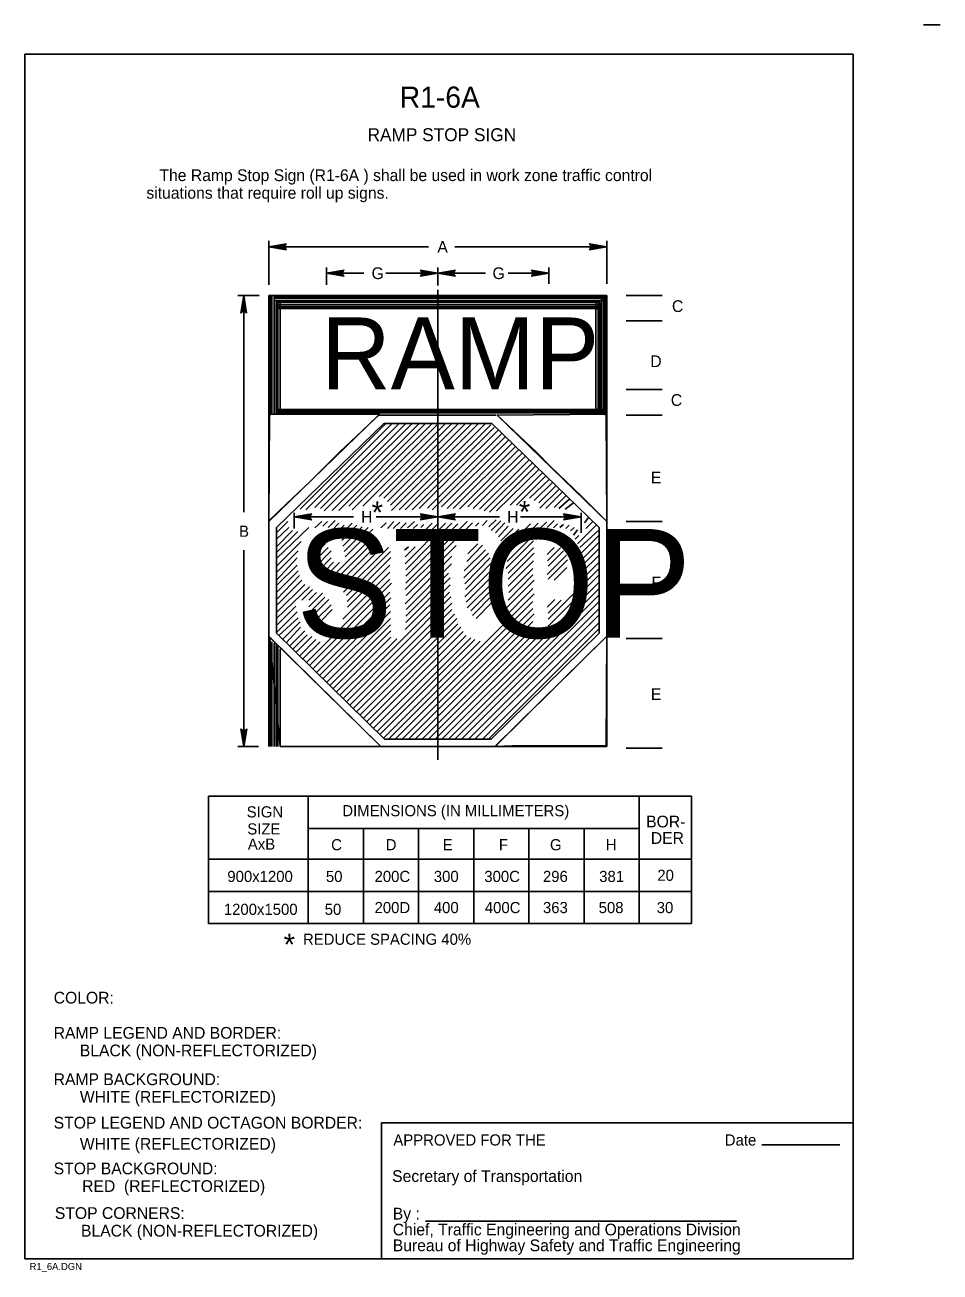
# Model space of a CAD drawing. Extents: x -0.162 to 0.195, y -0.006 to 0.263.
# Drawn here: x 0 to 0.195, y -0.0028 to 0.2627 of the extents above; entities that cross this region are included whole.
import ezdxf

# ---------------------------------------------------------------- set-up
doc = ezdxf.new("R2010")
doc.units = 0
for name, color, linetype in [('1', 7, 'Continuous'), ('2', 7, 'Continuous'), ('3', 7, 'Continuous')]:
    doc.layers.add(name, color=color, linetype=linetype)

# ---------------------------------------------------------------- blocks, each defined once
blk = doc.blocks.new('RARROW')
at = {"layer": '3'}
for p, q in [((-2.156, 0.285), (-2.2665, 0.384625)), ((-2.2665, 0.384625), (0, 0)), ((0, 0), (-2.2665, -0.379125)), ((-2.156, 0.285), (-2.075625, 0.12075)), ((0, 0), (-2.156, 0.285)), ((-2.14975, -0.2705), (0, 0)), ((-2.075625, 0.12075), (0, 0)), ((0, 0), (-2.074, -0.108)), ((-2.2665, -0.379125), (-2.14975, -0.2705)), ((-2.074, -0.108), (-2.14975, -0.2705))]:
    blk.add_line(p, q, dxfattribs=at)

msp = doc.modelspace()

# ---------------------------------------------------------------- linework, layer by layer
at = {"layer": '1'}
for p, q in [((0.195, 0.26275), (0.1915, 0.26275)), ((0.1765, 0.2565), (0, 0.2565)), ((0, 0.2565), (0, 0)), ((0.1765, 0), (0.1765, 0.2565)), ((0.088, 0.20638), (0.088, 0.10625)), ((0.05738, 0.15888), (0.05738, 0.1555)), ((0.1185, 0.15888), (0.1185, 0.15463)), ((0.076, 0.029), (0.1765, 0.029)), ((0.076, 0.029), (0.076, 0)), ((0.157, 0.02425), (0.17363, 0.02425)), ((0.08538, 0.008), (0.15163, 0.008)), ((0, 0), (0.1765, 0))]:
    msp.add_line(p, q, dxfattribs=at)
at = {"layer": '3'}
for p, q in [((0.052, 0.20738), (0.052, 0.21675)), ((0.086, 0.2155), (0.052, 0.2155)), ((0.09162, 0.2155), (0.124, 0.2155)), ((0.124, 0.20763), (0.124, 0.21675)), ((0.06425, 0.20738), (0.06425, 0.21113)), ((0.07225, 0.20988), (0.06425, 0.20988)), ((0.07687, 0.20988), (0.088, 0.20988)), ((0.088, 0.20725), (0.088, 0.21113)), ((0.09813, 0.20988), (0.088, 0.20988)), ((0.103, 0.20988), (0.11163, 0.20988)), ((0.11163, 0.20763), (0.11163, 0.21113)), ((0.04988, 0.20513), (0.04537, 0.20513)), ((0.04662, 0.159), (0.04662, 0.20513)), ((0.052, 0.20513), (0.124, 0.20513)), ((0.052, 0.20513), (0.052, 0.10912)), ((0.05225, 0.17963), (0.05225, 0.205)), ((0.05262, 0.17988), (0.05262, 0.205)), ((0.05312, 0.17975), (0.05312, 0.205)), ((0.05325, 0.20488), (0.12312, 0.20488)), ((0.05325, 0.2045), (0.12312, 0.2045)), ((0.12287, 0.17975), (0.12287, 0.205)), ((0.12325, 0.17988), (0.12325, 0.205)), ((0.12362, 0.17963), (0.12362, 0.205)), ((0.124, 0.20513), (0.124, 0.10912)), ((0.12812, 0.20513), (0.13575, 0.20513)), ((0.05325, 0.204), (0.12312, 0.204)), ((0.0535, 0.20363), (0.1225, 0.20363)), ((0.0535, 0.17975), (0.0535, 0.20363)), ((0.0535, 0.20312), (0.1225, 0.20312)), ((0.0535, 0.20275), (0.1225, 0.20275)), ((0.0535, 0.20237), (0.1225, 0.20237)), ((0.05387, 0.18088), (0.05387, 0.20363)), ((0.05437, 0.18088), (0.05437, 0.20363)), ((0.12162, 0.18088), (0.12162, 0.20363)), ((0.12212, 0.18088), (0.12212, 0.20363)), ((0.1225, 0.17975), (0.1225, 0.20363)), ((0.12812, 0.19975), (0.13575, 0.19975)), ((0.12812, 0.18513), (0.13575, 0.18513)), ((0.0535, 0.18088), (0.124, 0.18088)), ((0.07537, 0.17963), (0.052, 0.157)), ((0.0535, 0.1805), (0.124, 0.1805)), ((0.0535, 0.18013), (0.124, 0.18013)), ((0.07537, 0.17963), (0.10038, 0.17963)), ((0.10063, 0.17963), (0.124, 0.157)), ((0.12812, 0.17963), (0.13575, 0.17963)), ((0.0765, 0.17788), (0.05362, 0.15575)), ((0.05863, 0.15963), (0.07687, 0.17788)), ((0.05988, 0.1595), (0.07825, 0.17788)), ((0.06175, 0.16), (0.07975, 0.17788)), ((0.063, 0.15975), (0.08113, 0.17788)), ((0.06375, 0.15925), (0.0825, 0.17788)), ((0.0655, 0.15938), (0.084, 0.17788)), ((0.06688, 0.15938), (0.08538, 0.17788)), ((0.069, 0.16025), (0.08675, 0.17788)), ((0.06975, 0.1595), (0.08812, 0.17788)), ((0.072, 0.16025), (0.08962, 0.17788)), ((0.0755, 0.16237), (0.091, 0.17788)), ((0.0765, 0.17788), (0.0995, 0.17788)), ((0.0765, 0.162), (0.09237, 0.17788)), ((0.07725, 0.16125), (0.09388, 0.17788)), ((0.07787, 0.1605), (0.09525, 0.17788)), ((0.07812, 0.15938), (0.09663, 0.17788)), ((0.07975, 0.1595), (0.09813, 0.17788)), ((0.081, 0.1595), (0.09925, 0.17763)), ((0.0825, 0.1595), (0.1, 0.177)), ((0.084, 0.15975), (0.10088, 0.1765)), ((0.08575, 0.15988), (0.10163, 0.17575)), ((0.0995, 0.17788), (0.12237, 0.15575)), ((0.08675, 0.1595), (0.10238, 0.17513)), ((0.08875, 0.16012), (0.10313, 0.17438)), ((0.09, 0.15975), (0.10388, 0.17375)), ((0.09125, 0.15975), (0.1045, 0.173)), ((0.09262, 0.15963), (0.10525, 0.17238)), ((0.09438, 0.16012), (0.106, 0.17162)), ((0.0955, 0.15975), (0.10662, 0.17087)), ((0.09688, 0.15963), (0.1075, 0.17025)), ((0.09788, 0.15925), (0.10812, 0.1695)), ((0.099, 0.159), (0.10887, 0.16887)), ((0.1005, 0.15925), (0.1095, 0.16812)), ((0.10338, 0.1605), (0.11025, 0.16737)), ((0.10475, 0.1605), (0.111, 0.16675)), ((0.1075, 0.162), (0.11175, 0.166)), ((0.1085, 0.1615), (0.1125, 0.16537)), ((0.1095, 0.161), (0.11313, 0.16462)), ((0.10975, 0.15988), (0.11388, 0.164)), ((0.111, 0.15975), (0.1145, 0.16325)), ((0.11275, 0.16), (0.11538, 0.16262)), ((0.11375, 0.15975), (0.11613, 0.16187)), ((0.11513, 0.15963), (0.11688, 0.161)), ((0.05375, 0.15475), (0.056, 0.157)), ((0.07, 0.158), (0.05738, 0.158)), ((0.06175, 0.15563), (0.06325, 0.157)), ((0.0635, 0.156), (0.0645, 0.157)), ((0.06463, 0.15575), (0.06613, 0.15725)), ((0.07487, 0.158), (0.088, 0.158)), ((0.07587, 0.15563), (0.077, 0.15675)), ((0.07725, 0.1555), (0.07863, 0.157)), ((0.0785, 0.1555), (0.07988, 0.15688)), ((0.08, 0.1555), (0.08125, 0.15675)), ((0.081, 0.1425), (0.09538, 0.15675)), ((0.08113, 0.14388), (0.09425, 0.157)), ((0.0815, 0.15563), (0.083, 0.157)), ((0.10113, 0.158), (0.088, 0.158)), ((0.096, 0.156), (0.09675, 0.15675)), ((0.0975, 0.15613), (0.0985, 0.15725)), ((0.09888, 0.15588), (0.10038, 0.15738)), ((0.09938, 0.15513), (0.10138, 0.15713)), ((0.10025, 0.15463), (0.10225, 0.15675)), ((0.10562, 0.158), (0.1185, 0.158)), ((0.10975, 0.1555), (0.11113, 0.15688)), ((0.11125, 0.15575), (0.11275, 0.15725)), ((0.11925, 0.15675), (0.12012, 0.15788)), ((0.1195, 0.1555), (0.121, 0.157)), ((0.12812, 0.157), (0.13575, 0.157)), ((0.05362, 0.13325), (0.05362, 0.15575)), ((0.05362, 0.14913), (0.0605, 0.15575)), ((0.05362, 0.15325), (0.05625, 0.15575)), ((0.05362, 0.15038), (0.05813, 0.15488)), ((0.05375, 0.15175), (0.057, 0.15513)), ((0.06538, 0.15513), (0.06688, 0.15663)), ((0.0665, 0.15475), (0.068, 0.15625)), ((0.06675, 0.15375), (0.06975, 0.15663)), ((0.0675, 0.153), (0.07075, 0.15625)), ((0.06775, 0.15175), (0.07188, 0.15588)), ((0.068, 0.15063), (0.07312, 0.15575)), ((0.06825, 0.1495), (0.07412, 0.15538)), ((0.081, 0.148), (0.08962, 0.15663)), ((0.08113, 0.14675), (0.091, 0.15663)), ((0.08113, 0.14538), (0.09225, 0.1565)), ((0.08275, 0.1555), (0.08363, 0.15638)), ((0.08438, 0.15575), (0.085, 0.15638)), ((0.085, 0.15488), (0.08675, 0.15663)), ((0.08525, 0.15375), (0.08812, 0.15663)), ((0.10088, 0.15375), (0.103, 0.156)), ((0.10138, 0.15288), (0.104, 0.1555)), ((0.10175, 0.152), (0.10525, 0.15538)), ((0.10213, 0.15088), (0.10775, 0.1565)), ((0.1025, 0.14975), (0.10938, 0.15663)), ((0.10275, 0.1485), (0.1085, 0.15425)), ((0.11263, 0.15563), (0.1135, 0.1565)), ((0.114, 0.15575), (0.11475, 0.15638)), ((0.11525, 0.1555), (0.116, 0.15625)), ((0.11625, 0.155), (0.117, 0.15575)), ((0.11688, 0.15413), (0.11775, 0.15525)), ((0.11775, 0.15225), (0.12175, 0.15625)), ((0.11825, 0.1515), (0.12237, 0.15525)), ((0.1185, 0.15025), (0.12237, 0.15413)), ((0.12237, 0.15575), (0.12237, 0.13325)), ((0.05362, 0.1475), (0.05888, 0.15275)), ((0.06087, 0.14913), (0.064, 0.15225)), ((0.06112, 0.148), (0.06463, 0.1515)), ((0.06575, 0.1455), (0.07375, 0.1535)), ((0.06675, 0.14513), (0.07387, 0.15225)), ((0.06725, 0.14425), (0.0745, 0.1515)), ((0.06788, 0.142), (0.0775, 0.1515)), ((0.06813, 0.14363), (0.076, 0.1515)), ((0.08088, 0.15088), (0.08175, 0.15163)), ((0.081, 0.1495), (0.08313, 0.15163)), ((0.08125, 0.14125), (0.09187, 0.15188)), ((0.09413, 0.1485), (0.0975, 0.152)), ((0.09438, 0.15013), (0.0965, 0.15225)), ((0.1025, 0.147), (0.10837, 0.15288)), ((0.103, 0.146), (0.10837, 0.15138)), ((0.11125, 0.15), (0.11275, 0.1515)), ((0.11138, 0.14863), (0.11413, 0.15138)), ((0.11725, 0.15325), (0.118, 0.154)), ((0.1185, 0.14875), (0.12237, 0.15263)), ((0.04662, 0.15088), (0.04662, 0.10912)), ((0.05362, 0.14613), (0.05825, 0.15075)), ((0.05362, 0.1445), (0.058, 0.14925)), ((0.06175, 0.14725), (0.06525, 0.15075)), ((0.06275, 0.14675), (0.06525, 0.14925)), ((0.0685, 0.14125), (0.07787, 0.15063)), ((0.06863, 0.14), (0.078, 0.14938)), ((0.081, 0.1395), (0.091, 0.14963)), ((0.0935, 0.145), (0.09875, 0.15025)), ((0.09362, 0.1465), (0.09813, 0.151)), ((0.09375, 0.14375), (0.09913, 0.14925)), ((0.103, 0.14475), (0.1085, 0.15025)), ((0.11125, 0.14575), (0.11538, 0.14988)), ((0.1115, 0.1475), (0.11475, 0.15075)), ((0.1115, 0.14475), (0.11563, 0.14888)), ((0.11863, 0.14613), (0.12237, 0.14988)), ((0.11875, 0.14763), (0.12237, 0.15125)), ((0.05362, 0.14338), (0.058, 0.14775)), ((0.05362, 0.14188), (0.05825, 0.1465)), ((0.064, 0.1465), (0.06575, 0.14838)), ((0.06513, 0.14638), (0.067, 0.14825)), ((0.06775, 0.13625), (0.07775, 0.14625)), ((0.06875, 0.13875), (0.07775, 0.14775)), ((0.08125, 0.13825), (0.09087, 0.148)), ((0.09375, 0.141), (0.09963, 0.14688)), ((0.09388, 0.1425), (0.09938, 0.14813)), ((0.103, 0.14325), (0.10837, 0.14863)), ((0.10313, 0.14188), (0.10825, 0.147)), ((0.1115, 0.13625), (0.12237, 0.147)), ((0.11275, 0.1445), (0.1155, 0.14725)), ((0.118, 0.144), (0.12237, 0.14838)), ((0.05362, 0.14037), (0.0585, 0.1455)), ((0.05362, 0.13912), (0.059, 0.1445)), ((0.05362, 0.13762), (0.05963, 0.14363)), ((0.06, 0.127), (0.07775, 0.14475)), ((0.06062, 0.12638), (0.07812, 0.14388)), ((0.081, 0.134), (0.09062, 0.1435)), ((0.08113, 0.13687), (0.09025, 0.146)), ((0.08113, 0.1355), (0.09062, 0.145)), ((0.094, 0.13987), (0.09988, 0.14575)), ((0.09425, 0.13862), (0.09975, 0.14413)), ((0.10225, 0.13825), (0.1085, 0.1445)), ((0.103, 0.14025), (0.10825, 0.14563)), ((0.1115, 0.13475), (0.12237, 0.14563)), ((0.1115, 0.13325), (0.12237, 0.14413)), ((0.05362, 0.13637), (0.06062, 0.14313)), ((0.059, 0.14025), (0.06125, 0.1425)), ((0.0605, 0.14025), (0.06212, 0.14188)), ((0.0605, 0.13887), (0.06338, 0.14175)), ((0.06075, 0.13775), (0.06388, 0.14088)), ((0.06137, 0.12563), (0.07775, 0.142)), ((0.06212, 0.12487), (0.078, 0.14075)), ((0.06775, 0.11925), (0.0905, 0.142)), ((0.0685, 0.11863), (0.09075, 0.141)), ((0.0775, 0.11063), (0.1085, 0.14163)), ((0.09025, 0.11063), (0.12237, 0.14275)), ((0.09162, 0.11063), (0.12237, 0.14138)), ((0.095, 0.138), (0.09975, 0.14275)), ((0.09538, 0.137), (0.09975, 0.1415)), ((0.10138, 0.13587), (0.10825, 0.14275)), ((0.05362, 0.13487), (0.05775, 0.139)), ((0.06112, 0.13675), (0.06475, 0.14037)), ((0.06212, 0.13625), (0.06525, 0.13925)), ((0.06275, 0.12425), (0.07775, 0.13925)), ((0.06313, 0.13587), (0.0655, 0.13825)), ((0.06925, 0.11788), (0.091, 0.13962)), ((0.07, 0.11725), (0.091, 0.13825)), ((0.07888, 0.11063), (0.10825, 0.14)), ((0.08038, 0.11063), (0.10825, 0.1385)), ((0.093, 0.11063), (0.12237, 0.14)), ((0.0945, 0.11063), (0.12237, 0.1385)), ((0.09613, 0.13637), (0.09938, 0.13962)), ((0.11125, 0.13875), (0.11288, 0.14037)), ((0.1115, 0.1375), (0.11425, 0.14025)), ((0.05362, 0.13337), (0.058, 0.13775)), ((0.05412, 0.13275), (0.05825, 0.1365)), ((0.055, 0.132), (0.05863, 0.13562)), ((0.0635, 0.1235), (0.07787, 0.13787)), ((0.06425, 0.12275), (0.07787, 0.13637)), ((0.07063, 0.1165), (0.0915, 0.13725)), ((0.07138, 0.11575), (0.092, 0.13637)), ((0.08175, 0.11063), (0.1085, 0.13737)), ((0.08313, 0.11063), (0.10825, 0.13575)), ((0.09588, 0.11063), (0.12237, 0.13712)), ((0.0975, 0.11063), (0.12237, 0.1355)), ((0.05362, 0.13325), (0.07662, 0.11063)), ((0.05575, 0.13125), (0.05875, 0.1345)), ((0.05638, 0.1305), (0.05963, 0.13375)), ((0.05713, 0.12987), (0.06012, 0.13287)), ((0.065, 0.12212), (0.07787, 0.135)), ((0.06563, 0.12137), (0.078, 0.13375)), ((0.07212, 0.11513), (0.09225, 0.13525)), ((0.07275, 0.11438), (0.09287, 0.1345)), ((0.0735, 0.11375), (0.09337, 0.13362)), ((0.08463, 0.11063), (0.1085, 0.1345)), ((0.086, 0.11063), (0.10825, 0.13287)), ((0.09875, 0.11063), (0.12225, 0.13412)), ((0.12237, 0.13325), (0.09938, 0.11063)), ((0.052, 0.13262), (0.07587, 0.10912)), ((0.05225, 0.10912), (0.05225, 0.13162)), ((0.05262, 0.10912), (0.05262, 0.13137)), ((0.05312, 0.10912), (0.05312, 0.13112)), ((0.0535, 0.10912), (0.0535, 0.13087)), ((0.05387, 0.10912), (0.05387, 0.13037)), ((0.05775, 0.12912), (0.06112, 0.1325)), ((0.0585, 0.12837), (0.062, 0.13187)), ((0.05925, 0.12775), (0.06288, 0.13137)), ((0.06638, 0.12075), (0.078, 0.13237)), ((0.06713, 0.12), (0.07925, 0.132)), ((0.07425, 0.113), (0.094, 0.13275)), ((0.075, 0.11225), (0.095, 0.13225)), ((0.07562, 0.11163), (0.09588, 0.13187)), ((0.07637, 0.11088), (0.097, 0.1315)), ((0.08738, 0.11063), (0.109, 0.13225)), ((0.08887, 0.11063), (0.1105, 0.13225)), ((0.124, 0.13262), (0.10013, 0.10912)), ((0.12812, 0.13212), (0.13575, 0.13212)), ((0.05437, 0.10912), (0.05437, 0.12987)), ((0.04975, 0.10912), (0.04537, 0.10912)), ((0.124, 0.10912), (0.07587, 0.10912)), ((0.07587, 0.10912), (0.124, 0.10912)), ((0.09938, 0.11063), (0.07662, 0.11063)), ((0.12812, 0.10875), (0.13575, 0.10875)), ((0.03913, 0.0985), (0.142, 0.0985)), ((0.03913, 0.0985), (0.03913, 0.07138)), ((0.06037, 0.0985), (0.06037, 0.07138)), ((0.13087, 0.0985), (0.13087, 0.07138)), ((0.13087, 0.0985), (0.13087, 0.07138)), ((0.142, 0.0985), (0.142, 0.07138)), ((0.13087, 0.09162), (0.06037, 0.09162)), ((0.07212, 0.09162), (0.07212, 0.07138)), ((0.08388, 0.09162), (0.08388, 0.07138)), ((0.09563, 0.09162), (0.09563, 0.07138)), ((0.10737, 0.09162), (0.10737, 0.07138)), ((0.11913, 0.09162), (0.11913, 0.07138)), ((0.03913, 0.08513), (0.142, 0.08513)), ((0.03913, 0.07825), (0.142, 0.07825)), ((0.03913, 0.07138), (0.142, 0.07138))]:
    msp.add_line(p, q, dxfattribs=at)
for points in [[(0.07562, 0.17988), (0.05212, 0.17988), (0.052, 0.15713), (0.05575, 0.16075), (0.06062, 0.16537), (0.067, 0.17175)], [(0.10063, 0.17963), (0.12387, 0.17988), (0.124, 0.157), (0.11875, 0.16225), (0.112, 0.16875), (0.109, 0.17175)], [(0.05212, 0.13237), (0.05437, 0.10912), (0.07587, 0.10912)], [(0.10388, 0.10925), (0.12387, 0.10925), (0.124, 0.13262), (0.10063, 0.1095), (0.10025, 0.10912)]]:
    msp.add_lwpolyline(points, close=True, dxfattribs=at)

# ---------------------------------------------------------------- block references
at = {"layer": '3', "xscale": 0.0016545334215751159, "yscale": 0.0016366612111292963}
for p, rotation in [((0.052, 0.2155), 180), ((0.06425, 0.20988), 180), ((0.088, 0.20988), 180), ((0.04662, 0.20513), 90), ((0.05738, 0.158), 180), ((0.088, 0.158), 180), ((0.04662, 0.10912), -90)]:
    msp.add_blockref('RARROW', p, dxfattribs=dict(at, rotation=rotation))
for p in [(0.124, 0.2155), (0.088, 0.20988), (0.11163, 0.20988), (0.088, 0.158), (0.1185, 0.158)]:
    msp.add_blockref('RARROW', p, dxfattribs=at)

# ---------------------------------------------------------------- texts
at = {"layer": '1'}
for s, height, p in [('R1-6A', 0.0045, (0.07988, 0.24513)), ('RAMP STOP SIGN', 0.0027503, (0.073, 0.238)), ('COLOR:', 0.0025, (0.00613, 0.05437)), ('RAMP LEGEND AND BORDER:', 0.0024998, (0.00613, 0.04688)), ('      BLACK (NON-REFLECTORIZED)', 0.0024998, (0.00613, 0.04313)), ('RAMP BACKGROUND:', 0.0024998, (0.00613, 0.037)), ('      WHITE (REFLECTORIZED)', 0.0024998, (0.00613, 0.03325)), ('STOP LEGEND AND OCTAGON BORDER:', 0.0024998, (0.00613, 0.02775)), ('      WHITE (REFLECTORIZED)', 0.0024998, (0.00613, 0.02325)), ('APPROVED FOR THE', 0.0023752, (0.0785, 0.02413)), ('Date ', 0.002375, (0.14913, 0.02413)), ('STOP BACKGROUND:', 0.0024998, (0.00613, 0.018)), ('Secretary of Transportation', 0.0024998, (0.07825, 0.01638)), ('      RED  (REFLECTORIZED)', 0.0024998, (0.00662, 0.01425)), ('STOP CORNERS:', 0.0024998, (0.00638, 0.0085)), ('By :', 0.0025, (0.07838, 0.00838)), ('      BLACK (NON-REFLECTORIZED)', 0.0024998, (0.00638, 0.00475)), ('Chief, Traffic Engineering and Operations Division', 0.0024998, (0.07838, 0.005)), ('Bureau of Highway Safety and Traffic Engineering', 0.0024998, (0.07838, 0.00163)), ('R1_6A.DGN', 0.0015, (0.001, -0.00237))]:
    msp.add_text(s, height=height, dxfattribs=at).set_placement(p)
at = {"layer": '2'}
for s, p in [('   The Ramp Stop Sign (R1-6A ) shall be used in work zone traffic control', (0.02588, 0.2295)), ('situations that require roll up signs.', (0.02588, 0.22575))]:
    msp.add_text(s, height=0.0024998, dxfattribs=at).set_placement(p)
at = {"layer": '3'}
for s, height, p in [('A', 0.0025, (0.08788, 0.21425)), ('G', 0.0025, (0.07387, 0.20863)), ('G', 0.0025, (0.09963, 0.20863)), ('C', 0.0025, (0.13787, 0.20162)), ('RAMP', 0.01533, (0.06313, 0.18513)), ('D', 0.0025, (0.13325, 0.18988)), ('C', 0.0025, (0.13762, 0.18163)), ('E', 0.0025, (0.13337, 0.16512)), ('*', 0.00465, (0.07387, 0.15663)), ('*', 0.00465, (0.10525, 0.15675)), ('H', 0.0025, (0.07163, 0.15675)), ('H', 0.0025, (0.10275, 0.15675)), ('B', 0.00238, (0.04562, 0.15375)), ('STOP', 0.023156, (0.05775, 0.13225)), ('F', 0.0025, (0.1335, 0.14275)), ('E', 0.0025, (0.13337, 0.119)), ('SIGN', 0.002375, (0.04725, 0.094)), ('DIMENSIONS (IN MILLIMETERS)', 0.0023752, (0.06763, 0.09425)), ('BOR-', 0.0025, (0.13237, 0.09187)), ('SIZE', 0.002375, (0.04738, 0.09037)), ('DER', 0.0025, (0.13337, 0.08837)), ('AxB', 0.002375, (0.0475, 0.08713)), ('C', 0.00238, (0.06525, 0.087)), ('D', 0.00238, (0.07687, 0.087)), ('E', 0.00238, (0.089, 0.087)), ('F', 0.00238, (0.101, 0.087)), ('G', 0.00238, (0.11188, 0.087)), ('H', 0.00238, (0.12375, 0.087)), ('900x1200', 0.002375, (0.04313, 0.08025)), ('50', 0.002375, (0.06413, 0.08025)), ('200C', 0.002375, (0.0745, 0.08025)), ('300', 0.002375, (0.08713, 0.08025)), ('300C', 0.002375, (0.09788, 0.08025)), ('296', 0.002375, (0.11038, 0.08025)), ('381', 0.002375, (0.12237, 0.08025)), ('20', 0.002375, (0.13475, 0.0805)), ('1200x1500', 0.002375, (0.04238, 0.07325)), ('50', 0.002375, (0.06388, 0.07325)), ('200D', 0.002375, (0.0745, 0.07362)), ('400', 0.002375, (0.08713, 0.07362)), ('400C', 0.002375, (0.098, 0.07362)), ('363', 0.002375, (0.11038, 0.07362)), ('508', 0.002375, (0.12225, 0.07362)), ('30', 0.002375, (0.13462, 0.07362)), ('*', 0.00465, (0.05513, 0.06463)), ('REDUCE SPACING 40%', 0.0023752, (0.05925, 0.06688))]:
    msp.add_text(s, height=height, dxfattribs=at).set_placement(p)

doc.saveas('drawing.dxf')
